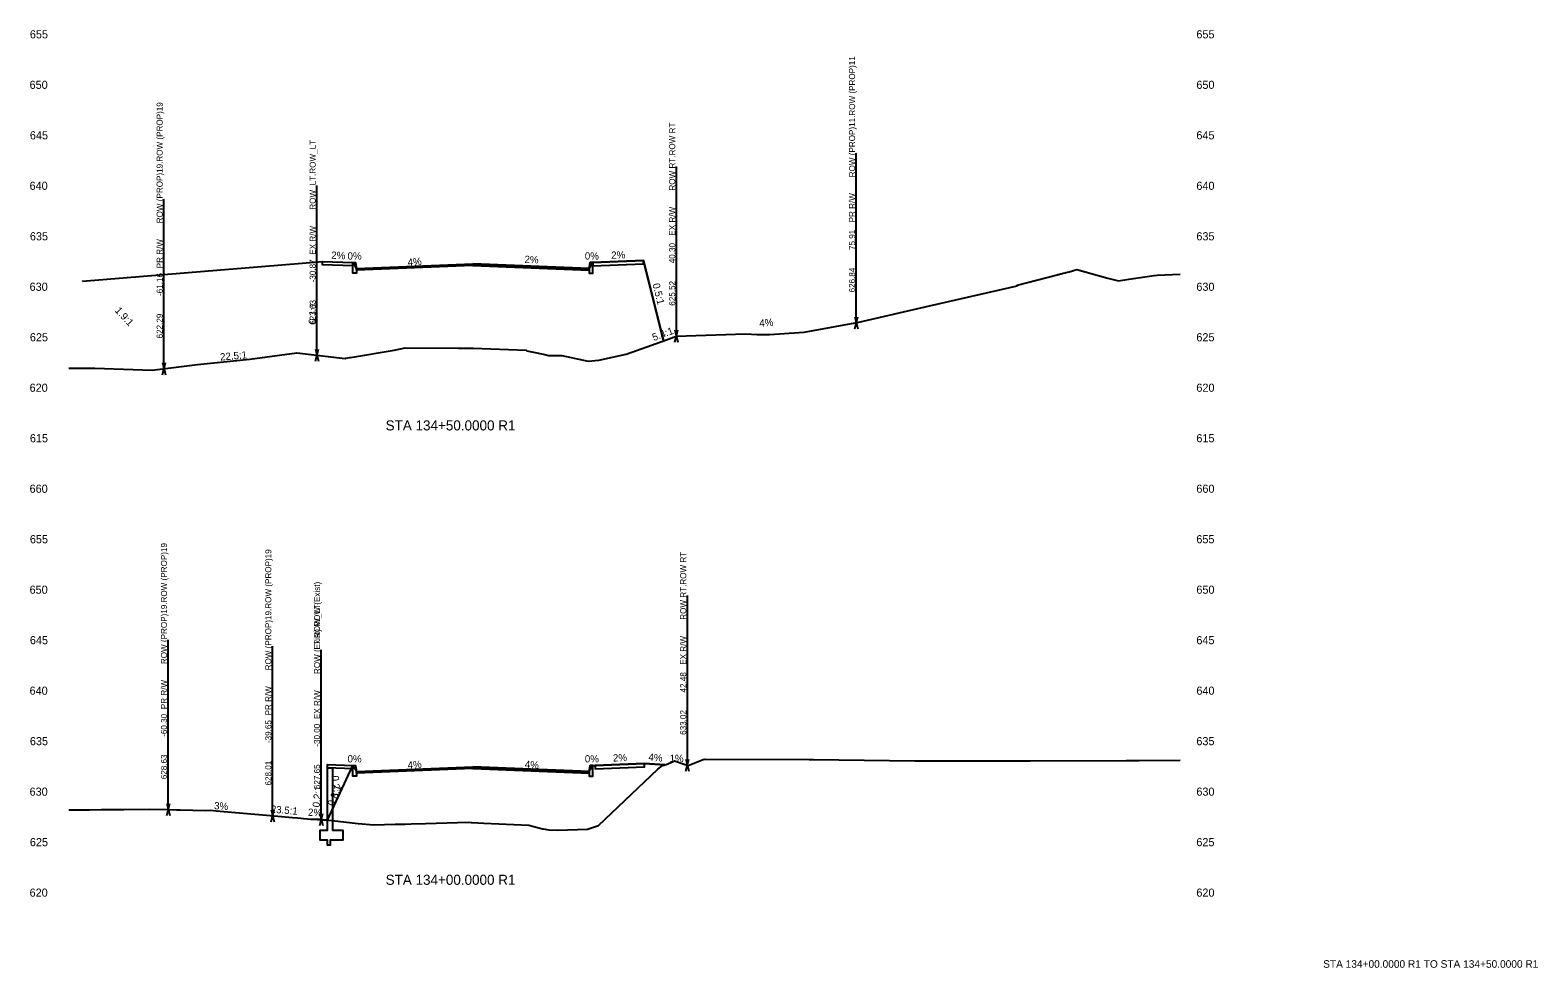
# Model space of a CAD drawing. Extents: x 2 to 741, y 16 to 2207.
# Drawn here: x 442.4 to 740.8, y 1365.9 to 1551.6 of the extents above; entities that cross this region are included whole.
import ezdxf

# ---------------------------------------------------------------- set-up
doc = ezdxf.new("R2010")
doc.units = 0
for name, color, linetype in [('BORD_text_large_2', 7, 'Continuous'), ('Draft_XS_Feature_Name', 7, 'Continuous'), ('Draft_XS_Label', 7, 'Continuous'), ('Draft_XS_Point_Label_Indicator', 7, 'Continuous'), ('Draft_XS_Terminator', 7, 'Continuous'), ('Draft_XS_Text', 7, 'Continuous'), ('E_ROW', 7, 'Continuous'), ('E_Terrain_Exterior', 7, 'Continuous'), ('E_Terrain_Points_Low', 7, 'Continuous'), ('Grade_Veg_Grass', 7, 'Continuous'), ('P_XS_Sections', 7, 'Continuous'), ('PROP_ROW', 7, 'Continuous'), ('Road_Curb', 7, 'Continuous'), ('Road_Pave_Asphalt', 7, 'Continuous'), ('Road_Sidewalk', 7, 'Continuous'), ('Struc_Wall', 7, 'Continuous'), ('Terrain_Design', 7, 'Continuous')]:
    doc.layers.add(name, color=color, linetype=linetype)

msp = doc.modelspace()

# ---------------------------------------------------------------- linework, layer by layer
at = {"layer": 'Draft_XS_Terminator'}
for p, q in [((605.91, 1493.68), (605.91, 1515.68)), ((570.3, 1491.05), (570.3, 1513.05)), ((499.13, 1487.27), (499.13, 1509.27)), ((468.84, 1484.57), (468.84, 1506.57)), ((572.48, 1406.05), (572.48, 1428.05)), ((469.7, 1397.26), (469.7, 1419.26)), ((490.35, 1396.02), (490.35, 1418.02)), ((500, 1395.3), (500, 1417.3)), ((500, 1395.3), (500, 1417.3))]:
    msp.add_line(p, q, dxfattribs=at)
at = {"layer": 'E_ROW'}
for p, q in [((570.3, 1491.05), (570.3, 1524.65)), ((499.13, 1487.27), (499.13, 1520.87)), ((570, 1489.85), (570.6, 1492.25)), ((570, 1492.25), (570.6, 1489.85)), ((498.83, 1486.07), (499.43, 1488.47)), ((498.83, 1488.47), (499.43, 1486.07)), ((572.48, 1406.05), (572.48, 1439.65)), ((500, 1395.3), (500, 1428.9)), ((500, 1395.3), (500, 1428.9)), ((572.18, 1404.85), (572.78, 1407.25)), ((572.18, 1407.25), (572.78, 1404.85)), ((499.7, 1394.1), (500.3, 1396.5)), ((499.7, 1396.5), (500.3, 1394.1)), ((499.7, 1394.1), (500.3, 1396.5)), ((499.7, 1396.5), (500.3, 1394.1))]:
    msp.add_line(p, q, dxfattribs=at)
at = {"layer": 'E_Terrain_Exterior'}
for points in [[(450, 1484.68), (455.19, 1484.66), (466.52, 1484.29), (475.48, 1485.39), (485.83, 1486.44), (495.17, 1487.73), (504.73, 1486.62), (504.88, 1486.63), (505.58, 1486.76), (505.8, 1486.8), (514.44, 1488.25), (515.66, 1488.53), (516.61, 1488.7), (527.19, 1488.66), (528.51, 1488.67), (528.53, 1488.67), (528.56, 1488.67), (529.25, 1488.66), (530.05, 1488.62), (540.59, 1488.24), (540.72, 1488.11), (542.01, 1487.84), (542.03, 1487.86), (544.25, 1487.38), (545.01, 1487.22), (547.64, 1487.17), (552.82, 1486.04), (554.92, 1486.27), (560.33, 1487.48), (568.31, 1490.3), (570.28, 1491.04), (583.98, 1491.46), (586.28, 1491.35), (588.73, 1491.38), (595.59, 1491.81), (606.44, 1493.77), (620.42, 1497.03), (637.72, 1500.98), (637.74, 1501.1), (645.67, 1503.16), (645.67, 1503.16), (645.69, 1503.17), (645.72, 1503.18), (645.74, 1503.18), (645.75, 1503.18), (645.8, 1503.2), (645.84, 1503.21), (645.84, 1503.21), (645.84, 1503.21), (645.88, 1503.22), (646, 1503.25), (646.02, 1503.26), (646.05, 1503.26), (646.1, 1503.28), (646.14, 1503.29), (646.16, 1503.29), (646.33, 1503.34), (646.49, 1503.38), (646.86, 1503.48), (646.9, 1503.49), (647.22, 1503.57), (647.36, 1503.61), (648.04, 1503.79), (649.56, 1504.19), (655.68, 1502.51), (656.5, 1502.29), (657.81, 1502), (659.83, 1502.3), (664.89, 1503.05), (665.49, 1503.08), (670, 1503.27)], [(450, 1397.21), (454.03, 1397.23), (456.51, 1397.24), (457.99, 1397.25), (460.9, 1397.26), (465.94, 1397.35), (469.49, 1397.26), (471.31, 1397.22), (472.08, 1397.2), (477.1, 1397.08), (478.06, 1397.11), (479.21, 1396.99), (490.69, 1395.99), (494.33, 1395.68), (495.28, 1395.6), (495.93, 1395.54), (496.45, 1395.5), (497.88, 1395.38), (499.78, 1395.32), (507.33, 1394.47), (510.38, 1394.24), (514.64, 1394.35), (516.61, 1394.38), (517.77, 1394.43), (520.63, 1394.49), (529.09, 1394.75), (529.67, 1394.72), (529.81, 1394.71), (532.19, 1394.59), (541.08, 1394.19), (543.81, 1393.42), (543.89, 1393.47), (545.07, 1393.22), (546.76, 1393.18), (552.7, 1393.34), (554.85, 1394.09), (566.62, 1405.27), (567.53, 1405.98), (568.25, 1406.16), (569.64, 1406.77), (569.9, 1406.88), (571.83, 1406.27), (572.61, 1406), (575.62, 1407.2), (575.92, 1407.25), (575.97, 1407.26), (596.55, 1407.18), (597.45, 1407.18), (617.48, 1406.9), (618.93, 1406.91), (638.41, 1406.91), (640.41, 1406.9), (659.33, 1407), (661.9, 1407), (670, 1407.05)]]:
    msp.add_lwpolyline(points, dxfattribs=at)
at = {"layer": 'Grade_Veg_Grass'}
for points in [[(452.72, 1501.93), (452.72, 1501.93), (500.25, 1505.83)], [(567.75, 1490.11), (563.75, 1505.99), (563.75, 1505.99)], [(553.75, 1405.99), (554.2, 1406.01)], [(567.99, 1406.1), (563.99, 1406.4), (563.99, 1406.4)], [(497.25, 1395.43), (501.25, 1395.18), (501.25, 1395.18)]]:
    msp.add_lwpolyline(points, dxfattribs=at)
at = {"layer": 'PROP_ROW'}
for p, q in [((605.91, 1493.68), (605.91, 1527.28)), ((468.84, 1484.57), (468.84, 1518.17)), ((605.61, 1492.48), (606.21, 1494.88)), ((605.61, 1494.88), (606.21, 1492.48)), ((468.54, 1483.37), (469.14, 1485.77)), ((468.54, 1485.77), (469.14, 1483.37)), ((469.7, 1397.26), (469.7, 1430.86)), ((490.35, 1396.02), (490.35, 1429.62)), ((469.4, 1396.06), (470, 1398.46)), ((469.4, 1398.46), (470, 1396.06)), ((490.05, 1394.82), (490.65, 1397.22)), ((490.05, 1397.22), (490.65, 1394.82))]:
    msp.add_line(p, q, dxfattribs=at)
at = {"layer": 'Road_Curb'}
for points in [[(507, 1504.42), (507, 1503.5), (506.25, 1503.5), (506.25, 1505.59), (506.77, 1505.59), (507, 1504.42)], [(553, 1504.42), (553, 1503.5), (553.75, 1503.5), (553.75, 1505.59), (553.23, 1505.59), (553, 1504.42)], [(507, 1404.82), (507, 1403.9), (506.25, 1403.9), (506.25, 1405.99), (506.77, 1405.99), (507, 1404.82)], [(553, 1404.82), (553, 1403.9), (553.75, 1403.9), (553.75, 1405.99), (553.23, 1405.99), (553, 1404.82)]]:
    msp.add_lwpolyline(points, dxfattribs=at)
at = {"layer": 'Road_Pave_Asphalt'}
for points in [[(530, 1505.34), (530, 1505.01), (507, 1504.09), (507, 1504.42), (530, 1505.34)], [(530, 1505.34), (530, 1505.01), (553, 1504.09), (553, 1504.42), (530, 1505.34)], [(530, 1405.74), (530, 1405.41), (507, 1404.49), (507, 1404.82), (530, 1405.74)], [(530, 1405.74), (530, 1405.41), (553, 1404.49), (553, 1404.82), (530, 1405.74)]]:
    msp.add_lwpolyline(points, dxfattribs=at)
at = {"layer": 'Road_Sidewalk'}
for points in [[(506.25, 1505.59), (506.25, 1504.92), (500.25, 1505.16), (500.25, 1505.83), (506.25, 1505.59)], [(553.75, 1505.59), (553.75, 1504.92), (563.75, 1505.32), (563.75, 1505.99), (553.75, 1505.59)], [(506.25, 1405.99), (506.25, 1405.32), (501.25, 1405.52), (501.25, 1406.19), (506.25, 1405.99)], [(554.2, 1406.01), (554.2, 1405.34), (563.99, 1405.73), (563.99, 1406.4), (554.2, 1406.01)]]:
    msp.add_lwpolyline(points, dxfattribs=at)
at = {"layer": 'Struc_Wall'}
msp.add_lwpolyline([(501.25, 1393.18), (501.25, 1395.18), (501.25, 1395.18), (501.25, 1405.52), (502.25, 1405.48), (502.25, 1405.48), (502.25, 1393.18), (502.25, 1393.18), (502.25, 1393.18), (504.25, 1393.18), (504.25, 1391.18), (504.25, 1391.18), (504.25, 1391.18), (501.75, 1391.18), (501.75, 1390.18), (501.75, 1390.18), (501.25, 1390.18), (501.25, 1390.18), (501.25, 1390.18), (501.25, 1391.18), (501.25, 1391.18), (499.75, 1391.18), (499.75, 1391.18), (499.75, 1393.18), (501.25, 1393.18), (501.25, 1393.18), (501.25, 1393.18)], dxfattribs=at)
at = {"layer": 'Terrain_Design'}
for points in [[(452.72, 1501.93), (452.72, 1501.93), (500.25, 1505.83), (506.25, 1505.59), (506.77, 1505.59), (507, 1504.42), (530, 1505.34), (553, 1504.42), (553.23, 1505.59), (553.75, 1505.59), (563.75, 1505.99), (567.75, 1490.11)], [(500.25, 1505.83), (500.25, 1505.83), (506.25, 1505.59), (506.77, 1504.78), (507, 1504.42), (530, 1505.34), (553, 1504.42), (553.23, 1504.78), (553.75, 1505.59), (563.75, 1505.99), (567.75, 1490.11)], [(497.25, 1395.43), (501.25, 1395.18), (506.25, 1405.99), (506.77, 1405.99), (507, 1404.82), (530, 1405.74), (553, 1404.82), (553.23, 1405.99), (553.75, 1405.99), (554.2, 1406.01), (563.99, 1406.4), (567.99, 1406.1)], [(501.25, 1406.19), (501.25, 1406.19), (506.25, 1405.99), (506.77, 1405.18), (507, 1404.82), (530, 1405.74), (553, 1404.82), (553.23, 1405.18), (553.75, 1405.99), (554.2, 1406.01), (563.99, 1406.4), (567.99, 1406.1)]]:
    msp.add_lwpolyline(points, dxfattribs=at)

# ---------------------------------------------------------------- texts
at = {"layer": 'BORD_text_large_2'}
msp.add_text('STA 134+00.0000 R1 TO STA 134+50.0000 R1', height=1.5, dxfattribs=at).set_placement((698.32, 1365.92))
at = {"layer": 'Draft_XS_Feature_Name'}
for s, p in [('ROW (PROP)11.ROW (PROP)11', (605.67, 1522.48)), ('ROW (PROP)19.ROW (PROP)19', (468.6, 1513.37)), ('ROW RT.ROW RT', (570.06, 1519.85)), ('ROW_LT.ROW_LT', (498.89, 1516.07)), ('ROW (PROP)19.ROW (PROP)19', (469.46, 1426.06)), ('ROW (PROP)19.ROW (PROP)19', (490.11, 1424.82)), ('ROW RT.ROW RT', (572.24, 1434.85)), ('ROW (Exist).ROW (Exist)', (499.76, 1424.1)), ('ROW_LT.ROW_LT', (499.76, 1424.1))]:
    msp.add_text(s, height=1.2, rotation=90, dxfattribs=at).set_placement(p)
at = {"layer": 'Draft_XS_Label'}
for s, p in [('75.91', (605.67, 1508.08)), ('40.30', (570.06, 1505.45)), ('-30.87', (498.89, 1501.67)), ('626.84', (605.67, 1499.68)), ('-61.16', (468.6, 1498.97)), ('625.52', (570.06, 1497.05)), ('622.29', (468.6, 1490.57)), ('623.63', (498.89, 1493.27)), ('42.48', (572.24, 1420.45)), ('-60.30', (469.46, 1411.66)), ('-39.65', (490.11, 1410.42)), ('633.02', (572.24, 1412.05)), ('-30.00', (499.76, 1409.7)), ('-30.00', (499.76, 1409.7)), ('628.63', (469.46, 1403.26)), ('628.01', (490.11, 1402.02)), ('627.65', (499.76, 1401.3)), ('627.65', (499.76, 1401.3))]:
    msp.add_text(s, height=1.2, rotation=90, dxfattribs=at).set_placement(p)
at = {"layer": 'Draft_XS_Point_Label_Indicator'}
for p in [(500.24, 1505.82), (506.24, 1505.58), (506.76, 1505.58), (506.99, 1504.41), (552.99, 1504.41), (553.22, 1505.58), (553.74, 1505.58), (563.74, 1505.98), (452.71, 1501.92), (506.99, 1503.49), (552.99, 1503.49), (567.74, 1490.1), (501.24, 1406.18), (506.24, 1405.98), (506.76, 1405.98), (553.22, 1405.98), (553.74, 1405.98), (554.19, 1405.99), (563.98, 1406.39), (567.98, 1406.09), (506.99, 1404.81), (506.99, 1403.89), (552.99, 1404.81), (552.99, 1403.89), (497.24, 1395.42), (502.16, 1395.17)]:
    msp.add_text('X', height=0.024, dxfattribs=at).set_placement(p)
at = {"layer": 'Draft_XS_Text'}
for s, height, p in [('655', 1.608, (442.32, 1550)), ('655', 1.608, (673.22, 1550)), ('650', 1.608, (442.26, 1540)), ('650', 1.608, (673.22, 1540)), ('645', 1.608, (442.32, 1530)), ('645', 1.608, (673.22, 1530)), ('640', 1.608, (442.26, 1520)), ('640', 1.608, (673.22, 1520)), ('635', 1.608, (442.32, 1510)), ('635', 1.608, (673.22, 1510)), ('630', 1.608, (442.26, 1500)), ('630', 1.608, (673.22, 1500)), ('625', 1.608, (442.32, 1490)), ('625', 1.608, (673.22, 1490)), ('620', 1.608, (442.26, 1480)), ('620', 1.608, (673.22, 1480)), ('STA 134+50.0000 R1', 1.992, (512.74, 1472.35)), ('615', 1.608, (442.32, 1470)), ('615', 1.608, (673.22, 1470)), ('660', 1.608, (442.26, 1460)), ('660', 1.608, (673.22, 1460)), ('655', 1.608, (442.32, 1450)), ('655', 1.608, (673.22, 1450)), ('650', 1.608, (442.26, 1440)), ('650', 1.608, (673.22, 1440)), ('645', 1.608, (442.32, 1430)), ('645', 1.608, (673.22, 1430)), ('640', 1.608, (442.26, 1420)), ('640', 1.608, (673.22, 1420)), ('635', 1.608, (442.32, 1410)), ('635', 1.608, (673.22, 1410)), ('630', 1.608, (442.26, 1400)), ('630', 1.608, (673.22, 1400)), ('625', 1.608, (442.32, 1390)), ('625', 1.608, (673.22, 1390)), ('STA 134+00.0000 R1', 1.992, (512.74, 1382.35)), ('620', 1.608, (442.26, 1380)), ('620', 1.608, (673.22, 1380))]:
    msp.add_text(s, height=height, dxfattribs=at).set_placement(p)
for s, rotation, p in [('2%', 357.7094, (501.96, 1506.36)), ('0%', 360, (505.2, 1506.19)), ('0%', 360, (552.17, 1506.19)), ('2%', 2.2906, (557.41, 1506.33)), ('4%', 4.5657, (517.14, 1504.92)), ('2%', 357.7094, (540.21, 1505.53)), ('0.5:1', 284.138, (565.55, 1501.3)), ('1.9:1', 312.874, (459.04, 1496.01)), ('0.1:1', 86.5577, (498.9, 1493.39)), ('5.4:1', 20.1523, (565.82, 1490.04)), ('4%', 4.2258, (586.75, 1492.86)), ('22.5:1', 5.0823, (480.03, 1486.17)), ('0%', 360, (505.2, 1406.59)), ('4%', 4.5657, (517.14, 1405.32)), ('4%', 355.4343, (540.24, 1405.53)), ('0%', 360, (552.17, 1406.59)), ('2%', 2.2906, (557.76, 1406.75)), ('4%', 355.7359, (564.72, 1406.94)), ('1%', 359.3301, (568.93, 1406.69)), ('0.2:1', 274.7595, (502.04, 1403.92)), ('0.2:1', 83.4526, (499.66, 1397.63)), ('0.8:1', 69.3056, (502.52, 1397.8)), ('3%', 356.5717, (478.75, 1397.32)), ('23.5:1', 355.1333, (489.95, 1396.66)), ('2%', 357.1813, (497.34, 1396.03))]:
    msp.add_text(s, height=1.44, rotation=rotation, dxfattribs=at).set_placement(p)
at = {"layer": 'E_ROW'}
for p in [(570.06, 1510.93), (498.89, 1507.15), (572.24, 1425.93), (499.76, 1415.18), (499.76, 1415.18)]:
    msp.add_text('EX R/W', height=1.2, rotation=90, dxfattribs=at).set_placement(p)
at = {"layer": 'E_Terrain_Points_Low'}
for p in [(529.99, 1505.33), (529.99, 1405.73)]:
    msp.add_text('X', height=0.024, dxfattribs=at).set_placement(p)
at = {"layer": 'P_XS_Sections'}
for p in [(450, 1470), (450, 1380)]:
    msp.add_text('-', height=0.0001, dxfattribs=at).set_placement(p)
at = {"layer": 'PROP_ROW'}
for p in [(605.67, 1513.56), (468.6, 1504.46), (469.46, 1417.14), (490.11, 1415.9)]:
    msp.add_text('PR R/W', height=1.2, rotation=90, dxfattribs=at).set_placement(p)

doc.saveas('drawing.dxf')
